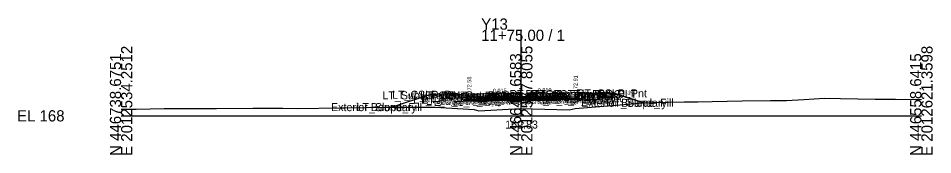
# Model space of a CAD drawing. Extents: x -26 to 1403, y -10 to 4517.
# Drawn here: x -25.7 to 202.8, y 3490.3 to 3524.3 of the extents above; entities that cross this region are included whole.
import ezdxf

# ---------------------------------------------------------------- set-up
doc = ezdxf.new("R2010")
doc.units = 0
for name, color, linetype in [('Default', 7, 'Continuous'), ('Exist Cross Section Cell', 7, 'Continuous'), ('Exist XS Center Line Elevation Label', 7, 'Continuous'), ('Exist XS Ground Line', 7, 'Continuous'), ('Prop CMT Conc Surface', 7, 'Continuous'), ('Prop CMT Concrete Structures', 7, 'Continuous'), ('Prop CMT Pvmt Course 1', 7, 'Continuous'), ('Prop CMT Pvmt Course 1 CG', 7, 'Continuous'), ('Prop CMT Pvmt Course 2', 7, 'Continuous'), ('Prop CMT Pvmt Course 3', 7, 'Continuous'), ('Prop CMT Pvmt Surface', 7, 'Continuous'), ('Prop CMT Slope Grass', 7, 'Continuous'), ('Prop CMT Subgrade Earthwork', 7, 'Continuous'), ('Prop XS Earthwork Shape', 7, 'Continuous'), ('Prop XS Hydro Elevations', 7, 'Continuous'), ('Prop XS SE Text', 7, 'Continuous'), ('Prop XS Side Slope Text', 7, 'Continuous'), ('Scratch_Level_0', 7, 'Continuous')]:
    doc.layers.add(name, color=color, linetype=linetype)

msp = doc.modelspace()

# ---------------------------------------------------------------- linework, layer by layer
at = {"layer": 'Exist Cross Section Cell'}
for p, q in [((100, 3500), (100, 3521.5)), ((0, 3500), (100, 3500)), ((100, 3500), (200, 3500))]:
    msp.add_line(p, q, dxfattribs=at)
at = {"layer": 'Exist XS Ground Line'}
msp.add_lwpolyline([(0, 3501.63), (3.74, 3501.69), (10.79, 3501.83), (23.87, 3501.83), (32.89, 3501.89), (40.46, 3501.92), (44.12, 3501.82), (54.66, 3501.97), (55.23, 3501.97), (55.85, 3501.98), (66.35, 3502.14), (70.41, 3502.18), (77.46, 3502.19), (78.53, 3502.15), (88.23, 3501.56), (89.41, 3501.28), (99.83, 3501.83), (111.98, 3501.51), (113.45, 3501.86), (124.76, 3502.76), (130.31, 3503.25), (133.01, 3503.33), (140.76, 3503.48), (144.12, 3503.51), (147.7, 3503.6), (155.23, 3503.73), (162.29, 3503.8), (166.34, 3503.81), (170.66, 3504.05), (175.83, 3504.37), (179.79, 3504.3), (188.47, 3504.18), (193.56, 3504.16), (200, 3504.08)], dxfattribs=at)
at = {"layer": 'Prop CMT Conc Surface'}
for points in [[(87.02, 3504.58), (87.02, 3505.08), (86.52, 3505.08)], [(89, 3504.69), (87.02, 3504.58)], [(111.58, 3504.97), (113.57, 3504.91)], [(113.57, 3504.91), (113.57, 3505.41), (114.06, 3505.41)]]:
    msp.add_lwpolyline(points, dxfattribs=at)
at = {"layer": 'Prop CMT Concrete Structures'}
for points in [[(89, 3504.69), (87.02, 3504.58), (87.02, 3505.08), (86.52, 3505.08)], [(86.52, 3505.08), (86.52, 3504.07), (89, 3504.1)], [(89, 3504.1), (89, 3504.69)], [(111.58, 3504.97), (113.57, 3504.91), (113.57, 3505.41), (114.06, 3505.41)], [(114.06, 3505.41), (114.06, 3504.41), (111.58, 3504.39)], [(111.58, 3504.39), (111.58, 3504.97)]]:
    msp.add_lwpolyline(points, dxfattribs=at)
at = {"layer": 'Prop CMT Pvmt Course 1'}
for points in [[(100, 3504.85), (89, 3504.69)], [(89, 3504.69), (89, 3504.44)], [(89, 3504.44), (100, 3504.6)], [(100, 3504.85), (111.58, 3504.97)], [(100, 3504.6), (100, 3504.85)], [(100, 3504.6), (100, 3504.85)], [(111.58, 3504.72), (100, 3504.6)], [(111.58, 3504.97), (111.58, 3504.72)]]:
    msp.add_lwpolyline(points, dxfattribs=at)
msp.add_lwpolyline([(100, 3504.6), (100, 3504.73), (100, 3504.73), (100, 3504.6)], close=True, dxfattribs=at)
msp.add_lwpolyline([(100, 3504.6), (100, 3504.73), (100, 3504.73), (100, 3504.6)], close=True, dxfattribs=at)
at = {"layer": 'Prop CMT Pvmt Course 1 CG'}
for points in [[(89, 3504.1), (86.03, 3504.06), (85.69, 3503.72)], [(85.69, 3503.72), (89, 3503.77)], [(89, 3503.77), (89, 3504.1)], [(111.58, 3504.39), (114.56, 3504.42), (114.89, 3504.09)], [(111.58, 3504.06), (111.58, 3504.39)], [(114.89, 3504.09), (111.58, 3504.06)]]:
    msp.add_lwpolyline(points, dxfattribs=at)
at = {"layer": 'Prop CMT Pvmt Course 2'}
for points in [[(100, 3504.6), (89, 3504.44)], [(89, 3504.44), (89, 3504.1)], [(89, 3504.1), (100, 3504.27)], [(100, 3504.6), (111.58, 3504.72)], [(100, 3504.27), (100, 3504.6)], [(100, 3504.27), (100, 3504.6)], [(111.58, 3504.39), (100, 3504.27)], [(111.58, 3504.72), (111.58, 3504.39)]]:
    msp.add_lwpolyline(points, dxfattribs=at)
at = {"layer": 'Prop CMT Pvmt Course 3'}
for points in [[(100, 3504.27), (89, 3504.1)], [(89, 3504.1), (89, 3503.77)], [(89, 3503.77), (100, 3503.94)], [(100, 3504.27), (111.58, 3504.39)], [(100, 3503.94), (100, 3504.27)], [(100, 3503.94), (100, 3504.27)], [(111.58, 3504.06), (100, 3503.94)], [(111.58, 3504.39), (111.58, 3504.06)]]:
    msp.add_lwpolyline(points, dxfattribs=at)
at = {"layer": 'Prop CMT Pvmt Surface'}
for points in [[(100, 3504.85), (89, 3504.69)], [(100, 3504.85), (111.58, 3504.97)]]:
    msp.add_lwpolyline(points, dxfattribs=at)
at = {"layer": 'Prop CMT Slope Grass'}
for p, q in [((77.1, 3505.27), (67.76, 3502.15)), ((123.49, 3505.6), (130.52, 3503.26))]:
    msp.add_line(p, q, dxfattribs=at)
for points in [[(86.52, 3505.08), (77.1, 3505.27)], [(114.06, 3505.41), (123.49, 3505.6)]]:
    msp.add_lwpolyline(points, dxfattribs=at)
at = {"layer": 'Prop CMT Subgrade Earthwork'}
for points in [[(89, 3503.77), (85.69, 3503.72), (84.3, 3505.12)], [(100, 3503.94), (89, 3503.77)], [(100, 3503.94), (111.58, 3504.06)], [(111.58, 3504.06), (114.89, 3504.09), (116.24, 3505.46)]]:
    msp.add_lwpolyline(points, dxfattribs=at)
at = {"layer": 'Prop XS Earthwork Shape'}
msp.add_lwpolyline([(89.41, 3501.28), (99.83, 3501.83), (111.98, 3501.51), (113.45, 3501.86), (124.76, 3502.76), (130.31, 3503.25), (130.52, 3503.26), (123.49, 3505.6), (116.24, 3505.46), (114.89, 3504.09), (111.58, 3504.06), (100, 3503.94), (89, 3503.77), (85.69, 3503.72), (84.3, 3505.12), (77.1, 3505.27), (67.76, 3502.15), (70.41, 3502.18), (77.46, 3502.19), (78.53, 3502.15), (88.23, 3501.56)], close=True, dxfattribs=at)

# ---------------------------------------------------------------- texts
at = {"layer": 'Default'}
msp.add_text('-', height=0.0001, dxfattribs=at).set_placement((0, 3500))
at = {"layer": 'Exist Cross Section Cell'}
for s, p in [('Y13', (90, 3521.5)), ('11+75.00 / 1', (90, 3518.7)), ('EL 168', (-26, 3498.6))]:
    msp.add_text(s, height=2.8, dxfattribs=at).set_placement(p)
for s, p in [('E 2012534.2512', (2.8, 3490)), ('E 2012577.8055', (102.8, 3490)), ('E 2012621.3598', (202.8, 3490)), ('N 446738.6751', (0, 3490)), ('N 446648.6583', (100, 3490)), ('N 446558.6415', (200, 3490))]:
    msp.add_text(s, height=2.8, rotation=90, dxfattribs=at).set_placement(p)
at = {"layer": 'Exist XS Center Line Elevation Label'}
msp.add_text('169.83', height=2, dxfattribs=at).set_placement((95.99, 3496.83))
at = {"layer": 'Prop XS Hydro Elevations'}
for s, p in [('172.58', (87.52, 3505.58)), ('172.91', (114.07, 3505.91))]:
    msp.add_text(s, height=1, rotation=90, dxfattribs=at).set_placement(p)
at = {"layer": 'Prop XS SE Text'}
for s, rotation, p in [('0.015', 0.8669, (92.92, 3505.75)), ('0.010', 0.5914, (104.13, 3505.9))]:
    msp.add_text(s, height=1, rotation=rotation, dxfattribs=at).set_placement(p)
at = {"layer": 'Prop XS Side Slope Text'}
for rotation, p in [(18.4332, (71.82, 3504.3)), (341.5668, (126.47, 3505.4))]:
    msp.add_text('3:1', height=1, rotation=rotation, dxfattribs=at).set_placement(p)
at = {"layer": 'Scratch_Level_0'}
for s, p in [('LT_Sub_Trench_Out_DLT', (65.29, 3504.12)), ('LT_CSLP_Pnt', (67.7, 3504.26)), ('LT_CG_Top_Face', (74.7, 3504.07)), ('LT_CG_Top_BOC', (75.23, 3504.07)), ('LT_PV1_OEOT', (80.16, 3503.68)), ('RT_PV1_OEEOP', (90.16, 3503.72)), ('LT_PV1_OEEOP', (90.2, 3503.72)), ('RT_PV1_IEEOP', (90.8, 3503.72)), ('LT_PV1_IEEOP', (90.85, 3503.72)), ('PV1_PGL', (94.8, 3503.85)), ('RT_Sub_Trench_Out_DLT', (97.04, 3504.45)), ('RT_CG_Top_Face', (101.06, 3504.41)), ('RT_PV2_OEOT', (101.99, 3503.72)), ('RT_CG_Top_Gut', (102.04, 3503.91)), ('RT_PV1_OEOT', (102.56, 3503.97)), ('RT_CG_Top_BOC', (102.58, 3504.41)), ('RT_CSLP_Pnt', (113.89, 3504.6)), ('LT_CG1_Shelf_Out', (73, 3503.05)), ('LT_CG_Bot_BOC', (75.26, 3503.06)), ('LT_CG_Top_Gut', (75.68, 3503.57)), ('LT_Sub_OEOP', (76.22, 3502.72)), ('LT_CG_Bot_IE', (79.34, 3503.1)), ('LT_Sub_OEOT', (79.5, 3502.77)), ('LT_PV2_OEOT', (79.6, 3503.43)), ('LT_PV3_OEOT', (79.6, 3503.1)), ('RT_Sub_OEEOP', (89.49, 3502.93)), ('LT_Sub_OEEOP', (89.54, 3502.93)), ('RT_PV2_OEEOP', (89.59, 3503.6)), ('RT_PV3_OEEOP', (89.59, 3503.26)), ('LT_PV2_OEEOP', (89.64, 3503.6)), ('LT_PV3_OEEOP', (89.64, 3503.26)), ('RT_PV2_IEEOP', (90.23, 3503.6)), ('LT_PV2_IEEOP', (90.28, 3503.6)), ('PV2_PGL', (94.23, 3503.6)), ('RT_CG1_Shelf_Out', (101.34, 3503.41)), ('RT_CG_Bot_IE', (101.73, 3503.38)), ('RT_Sub_OEOT', (101.9, 3503.05)), ('RT_PV3_OEOT', (101.99, 3503.38)), ('RT_CG_Bot_BOC', (102.61, 3503.41)), ('RT_Sub_OEOP', (105.23, 3503.08)), ('Exterior Boundary', (114.98, 3502.25)), ('RT_Slope_Fill', (121.31, 3502.25)), ('Exterior Boundary', (52.46, 3501.17)), ('LT_Slope_Fill', (58.84, 3501.17))]:
    msp.add_text(s, height=2, dxfattribs=at).set_placement(p)

doc.saveas('drawing.dxf')
